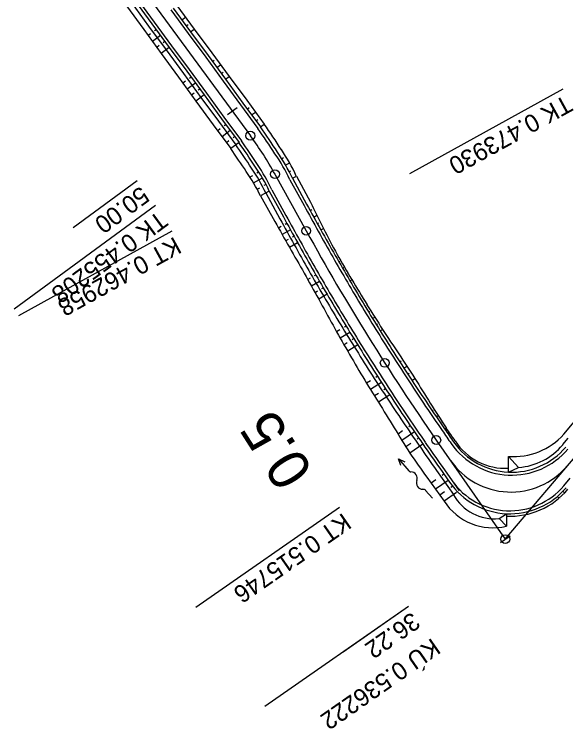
# Model space of a CAD drawing. Extents: x -481645 to -478728, y -1113199 to -1110710.
# Drawn here: x -480674.3 to -480580.8, y -1112993.4 to -1112872.3 of the extents above; entities that cross this region are included whole.
import ezdxf

# ---------------------------------------------------------------- set-up
doc = ezdxf.new("R2010")
doc.units = 0
for name, color, linetype in [('CP14_HATCH_SLOPE_R', 7, 'Continuous'), ('CP14_HECTOMETRY', 7, 'Continuous'), ('CP14_HLBODY', 7, 'Continuous'), ('CP14_STANICENI', 7, 'Continuous'), ('Vrstva 31', 7, 'Continuous'), ('Vrstva 32', 7, 'Continuous'), ('Vrstva 33', 7, 'Continuous'), ('Vrstva 34', 7, 'Continuous'), ('Vrstva 35', 7, 'Continuous'), ('Vrstva 36', 7, 'Continuous'), ('Vrstva 37', 7, 'Continuous'), ('Vrstva 38', 7, 'Continuous'), ('Vrstva 39', 7, 'Continuous'), ('Vrstva 40', 7, 'Continuous'), ('Vrstva 52', 7, 'Continuous'), ('Vrstva 53', 7, 'Continuous'), ('Vrstva 54', 7, 'Continuous'), ('Vrstva 56', 7, 'Continuous'), ('Vrstva 59', 7, 'Continuous'), ('Vrstva 60', 7, 'Continuous'), ('Vrstva 62', 7, 'Continuous')]:
    doc.layers.add(name, color=color, linetype=linetype)

# ---------------------------------------------------------------- blocks, each defined once
blk = doc.blocks.new('A$C70B')
at = {"layer": 'CP14_HLBODY'}
for p, q in [((0.87, 0), (-0.87, 0)), ((6.86, 0.43), (7.97, 0)), ((7.97, 0), (5.28, 0)), ((7.97, 0), (6.86, -0.48))]:
    blk.add_line(p, q, dxfattribs=at)
for centre, radius, start, end in [((0.87, 0.58), 0.582, 269.6924, 322.7901), ((2.17, -0.42), 1.05, 24.4039, 142.0836), ((4.08, 0.59), 1.11, 210.8873, 317.3707), ((5.32, -0.64), 0.636, 85.9766, 131.7248)]:
    blk.add_arc(centre, radius, start, end, dxfattribs=at)

msp = doc.modelspace()

# ---------------------------------------------------------------- linework, layer by layer
at = {"layer": 'CP14_HATCH_SLOPE_R'}
for p, q in [((-480664.72, -1112851.37), (-480634.28, -1112892.85)), ((-480630.11, -1112899.38), (-480624.81, -1112908.99)), ((-480602.74, -1112944.48), (-480591.03, -1112961.28))]:
    msp.add_line(p, q, dxfattribs=at)
for centre, radius, start, end in [((-480682.64, -1112928.36), 60, 28.8789, 36.2792), ((-480274.55, -1112715.8), 400, 208.8788, 214.8684)]:
    msp.add_arc(centre, radius, start, end, dxfattribs=at)
at = {"layer": 'CP14_STANICENI'}
for p, q in [((-480590.5, -1112949.92), (-480590.47, -1112947.25)), ((-480588.77, -1112949.11), (-480590.47, -1112947.25)), ((-480590.5, -1112949.92), (-480588.77, -1112949.11)), ((-480592.09, -1112957.8), (-480590.83, -1112956.97)), ((-480590.84, -1112959.08), (-480592.09, -1112957.8)), ((-480590.83, -1112956.97), (-480590.84, -1112959.08))]:
    msp.add_line(p, q, dxfattribs=at)
for centre, radius, start, end in [((-480589.58, -1112935.89), 11.4, 265.5343, 318.151), ((-480589.94, -1112937.91), 12.52, 214.9729, 319.6999), ((-480589.94, -1112937.91), 12.02, 214.9901, 319.698), ((-480591, -1112939.1), 10.17, 212.932, 273.0058), ((-480589.47, -1112938.55), 10.59, 273.8091, 320.6838), ((-480590.07, -1112940.8), 12.5, 214.8684, 319.744), ((-480590.24, -1112944.48), 12.5, 214.8684, 319.744), ((-480590.24, -1112944.48), 12, 214.8684, 319.744), ((-480590.24, -1112944.48), 12.91, 267.3062, 319.744), ((-480592.82, -1112949.79), 8.05, 209.4121, 275.245), ((-480593.17, -1112949.64), 9.72, 212.2087, 283.8922)]:
    msp.add_arc(centre, radius, start, end, dxfattribs=at)
at = {"layer": 'Vrstva 31'}
for p, q in [((-480655.3, -1112870.81), (-480652.35, -1112874.85)), ((-480646.77, -1112870.75), (-480643.8, -1112874.77)), ((-480652.35, -1112874.85), (-480649.41, -1112878.89)), ((-480643.8, -1112874.77), (-480640.83, -1112878.8)), ((-480649.41, -1112878.89), (-480646.46, -1112882.93)), ((-480640.83, -1112878.8), (-480637.86, -1112882.82)), ((-480646.46, -1112882.93), (-480643.51, -1112886.97)), ((-480637.86, -1112882.82), (-480634.9, -1112886.85)), ((-480643.51, -1112886.97), (-480640.57, -1112891.01)), ((-480634.9, -1112886.85), (-480631.93, -1112890.87)), ((-480640.57, -1112891.01), (-480637.62, -1112895.05)), ((-480626.48, -1112899.71), (-480624.1, -1112904.1)), ((-480632.56, -1112903.06), (-480630.11, -1112907.42)), ((-480604.34, -1112950.78), (-480601.4, -1112954.82))]:
    msp.add_line(p, q, dxfattribs=at)
for centre, radius, start, end in [((-480787.47, -1112998.49), 189.14, 33.0917, 34.6799), ((-480775.06, -1112991.79), 168.07, 33.5443, 35.1399), ((-480655.13, -1112912.86), 31.52, 24.6601, 34.0294), ((-480657.89, -1112915.03), 28.01, 25.2754, 35.1138), ((-479554.4, -1112378.75), 1191.74, 206.15703, 206.39731), ((-479573.29, -1112315.01), 1211.54, 209.27317, 209.51012), ((-480269.1, -1112725.81), 397.32, 207.3887, 208.1052), ((-480276.26, -1112712.8), 403.82, 209.5225, 210.2388), ((-480274.92, -1112715.17), 397.39, 209.8541, 210.5703), ((-480270.51, -1112722.94), 403.85, 208.5849, 209.3012), ((-480276.16, -1112713.12), 397.36, 210.9152, 211.6315), ((-480267.66, -1112727.81), 403.99, 208.5011, 209.2177), ((-480277.16, -1112711.61), 397.31, 211.8922, 212.6085), ((-480267.45, -1112727.83), 404.17, 209.1997, 209.9163), ((-480279.02, -1112708.87), 397.23, 213.0863, 213.8026), ((-480267.36, -1112727.64), 404.34, 209.9347, 210.6513), ((-480276.12, -1112713.4), 397.16, 213.0273, 213.7435), ((-480270.28, -1112722.52), 404.48, 211.485, 212.2014), ((-480267.71, -1112726.43), 397.22, 211.5063, 212.2229), ((-480266.47, -1112728.42), 404.62, 211.2066, 211.9233), ((-480268.31, -1112725.2), 397.37, 212.4186, 213.1351), ((-480265.04, -1112730.35), 404.82, 211.5848, 212.3017), ((-480654, -1112980.47), 65.2, 33.3455, 35.7109), ((-480439.82, -1112832.78), 202.47, 214.2314, 215.649)]:
    msp.add_arc(centre, radius, start, end, dxfattribs=at)
at = {"layer": 'Vrstva 32'}
for p, q in [((-480654.5, -1112870.23), (-480651.54, -1112874.26)), ((-480651.54, -1112874.26), (-480648.59, -1112878.29)), ((-480648.59, -1112878.29), (-480645.63, -1112882.32)), ((-480645.63, -1112882.32), (-480642.67, -1112886.35)), ((-480642.67, -1112886.35), (-480639.71, -1112890.38)), ((-480639.71, -1112890.38), (-480636.75, -1112894.41)), ((-480631.67, -1112902.57), (-480629.26, -1112906.95)), ((-480602.7, -1112949.64), (-480599.84, -1112953.74))]:
    msp.add_line(p, q, dxfattribs=at)
for centre, radius, start, end in [((-480777.22, -1112992.36), 171.25, 33.2939, 34.8884), ((-480657.58, -1112914.55), 28.54, 24.8176, 34.5767), ((-479569.79, -1112325.07), 1208.75, 208.77664, 209.01402), ((-480274.55, -1112715.8), 402.92, 209.0321, 209.7483), ((-480274.55, -1112715.8), 402.92, 209.7483, 210.4645), ((-480274.55, -1112715.8), 402.92, 210.4645, 211.1807), ((-480274.55, -1112715.8), 402.92, 211.1807, 211.8969), ((-480274.55, -1112715.8), 402.92, 211.8969, 212.6131), ((-480274.55, -1112715.8), 402.92, 212.6131, 213.3293), ((-480274.55, -1112715.8), 402.92, 213.3293, 214.0455), ((-480274.55, -1112715.8), 402.92, 214.0455, 214.7617), ((-480438.83, -1112832.44), 201.46, 214.1486, 215.5722)]:
    msp.add_arc(centre, radius, start, end, dxfattribs=at)
at = {"layer": 'Vrstva 33'}
for p, q in [((-480653.97, -1112869.83), (-480651.01, -1112873.86)), ((-480647.38, -1112871.2), (-480644.42, -1112875.23)), ((-480651.01, -1112873.86), (-480648.05, -1112877.89)), ((-480644.42, -1112875.23), (-480641.46, -1112879.26)), ((-480648.05, -1112877.89), (-480645.09, -1112881.92)), ((-480641.46, -1112879.26), (-480638.5, -1112883.29)), ((-480645.09, -1112881.92), (-480642.13, -1112885.95)), ((-480638.5, -1112883.29), (-480635.54, -1112887.32)), ((-480642.13, -1112885.95), (-480639.17, -1112889.99)), ((-480635.54, -1112887.32), (-480632.59, -1112891.35)), ((-480639.17, -1112889.99), (-480636.21, -1112894.02)), ((-480627.15, -1112900.08), (-480624.73, -1112904.46)), ((-480631.09, -1112902.25), (-480628.67, -1112906.63)), ((-480602.15, -1112949.26), (-480600.5, -1112951.63))]:
    msp.add_line(p, q, dxfattribs=at)
for centre, radius, start, end in [((-480785.79, -1112998.14), 186.75, 33.2888, 34.8776), ((-480778.33, -1112993.11), 173.25, 33.2932, 34.8869), ((-480655.35, -1112913.24), 31.12, 25.0179, 34.4356), ((-480657.29, -1112914.39), 28.88, 24.8453, 34.5569), ((-479578.83, -1112330.06), 1193.25, 208.77527, 209.01506), ((-479570.95, -1112325.71), 1206.75, 208.77647, 209.01415), ((-480274.55, -1112715.8), 397.75, 209.0321, 209.7483), ((-480274.55, -1112715.8), 402.25, 209.0321, 209.7483), ((-480274.55, -1112715.8), 397.75, 209.7483, 210.4645), ((-480274.55, -1112715.8), 402.25, 209.7483, 210.4645), ((-480274.55, -1112715.8), 397.75, 210.4645, 211.1807), ((-480274.55, -1112715.8), 402.25, 210.4645, 211.1807), ((-480274.55, -1112715.8), 397.75, 211.1807, 211.8969), ((-480274.55, -1112715.8), 402.25, 211.1807, 211.8969), ((-480274.55, -1112715.8), 397.75, 211.8969, 212.6131), ((-480274.55, -1112715.8), 402.25, 211.8969, 212.6131), ((-480274.55, -1112715.8), 397.75, 212.6131, 213.3293), ((-480274.55, -1112715.8), 402.25, 212.6131, 213.3293), ((-480274.55, -1112715.8), 397.75, 213.3293, 214.0455), ((-480274.55, -1112715.8), 402.25, 213.3293, 214.0455), ((-480274.55, -1112715.8), 397.75, 214.0455, 214.7617), ((-480274.55, -1112715.8), 402.25, 214.0455, 214.7617), ((-480436.71, -1112830.97), 198.88, 214.1408, 214.9166), ((-480438.56, -1112832.25), 201.12, 214.1476, 215.5732)]:
    msp.add_arc(centre, radius, start, end, dxfattribs=at)
at = {"layer": 'Vrstva 34'}
for p, q in [((-480653.56, -1112869.53), (-480650.6, -1112873.57)), ((-480647.78, -1112871.5), (-480644.82, -1112875.53)), ((-480650.6, -1112873.57), (-480647.64, -1112877.6)), ((-480644.82, -1112875.53), (-480641.86, -1112879.56)), ((-480647.64, -1112877.6), (-480644.69, -1112881.63)), ((-480641.86, -1112879.56), (-480638.91, -1112883.59)), ((-480644.69, -1112881.63), (-480641.73, -1112885.66)), ((-480638.91, -1112883.59), (-480635.95, -1112887.62)), ((-480641.73, -1112885.66), (-480638.77, -1112889.69)), ((-480635.95, -1112887.62), (-480632.99, -1112891.65)), ((-480638.77, -1112889.69), (-480635.81, -1112893.72)), ((-480627.59, -1112900.32), (-480625.17, -1112904.7)), ((-480630.65, -1112902.01), (-480628.24, -1112906.39)), ((-480601.74, -1112948.97), (-480598.88, -1112953.07))]:
    msp.add_line(p, q, dxfattribs=at)
for centre, radius, start, end in [((-480784.96, -1112997.58), 185.25, 33.2893, 34.8785), ((-480779.16, -1112993.67), 174.75, 33.2927, 34.8858), ((-480655.57, -1112913.37), 30.88, 24.9999, 34.4481), ((-480657.08, -1112914.26), 29.12, 24.8657, 34.5424), ((-479577.96, -1112329.57), 1194.75, 208.7754, 209.01496), ((-479571.83, -1112326.19), 1205.25, 208.77634, 209.01425), ((-480274.55, -1112715.8), 398.25, 209.0321, 209.7483), ((-480274.55, -1112715.8), 401.75, 209.0321, 209.7483), ((-480274.55, -1112715.8), 398.25, 209.7483, 210.4645), ((-480274.55, -1112715.8), 401.75, 209.7483, 210.4645), ((-480274.55, -1112715.8), 398.25, 210.4645, 211.1807), ((-480274.55, -1112715.8), 401.75, 210.4645, 211.1807), ((-480274.55, -1112715.8), 398.25, 211.1807, 211.8969), ((-480274.55, -1112715.8), 401.75, 211.1807, 211.8969), ((-480274.55, -1112715.8), 398.25, 211.8969, 212.6131), ((-480274.55, -1112715.8), 401.75, 211.8969, 212.6131), ((-480274.55, -1112715.8), 398.25, 212.6131, 213.3293), ((-480274.55, -1112715.8), 401.75, 212.6131, 213.3293), ((-480274.55, -1112715.8), 398.25, 213.3293, 214.0455), ((-480274.55, -1112715.8), 401.75, 213.3293, 214.0455), ((-480274.55, -1112715.8), 398.25, 214.0455, 214.7617), ((-480274.55, -1112715.8), 401.75, 214.0455, 214.7617), ((-480436.92, -1112831.11), 199.12, 214.1416, 214.9159), ((-480438.36, -1112832.11), 200.88, 214.1468, 215.574)]:
    msp.add_arc(centre, radius, start, end, dxfattribs=at)
at = {"layer": 'Vrstva 35'}
for p, q in [((-480653.56, -1112869.53), (-480650.6, -1112873.57)), ((-480647.78, -1112871.5), (-480644.82, -1112875.53)), ((-480650.6, -1112873.57), (-480647.64, -1112877.6)), ((-480644.82, -1112875.53), (-480641.86, -1112879.56)), ((-480647.64, -1112877.6), (-480644.69, -1112881.63)), ((-480641.86, -1112879.56), (-480638.91, -1112883.59)), ((-480644.69, -1112881.63), (-480641.73, -1112885.66)), ((-480638.91, -1112883.59), (-480635.95, -1112887.62)), ((-480641.73, -1112885.66), (-480638.77, -1112889.69)), ((-480635.95, -1112887.62), (-480632.99, -1112891.65)), ((-480638.77, -1112889.69), (-480635.81, -1112893.72)), ((-480627.59, -1112900.32), (-480625.17, -1112904.7)), ((-480630.65, -1112902.01), (-480628.24, -1112906.39)), ((-480601.74, -1112948.97), (-480598.88, -1112953.07))]:
    msp.add_line(p, q, dxfattribs=at)
for centre, radius, start, end in [((-480784.96, -1112997.58), 185.25, 33.2893, 34.8785), ((-480779.16, -1112993.67), 174.75, 33.2927, 34.8858), ((-480655.57, -1112913.37), 30.88, 24.9999, 34.4481), ((-480657.08, -1112914.26), 29.12, 24.8657, 34.5424), ((-479577.96, -1112329.57), 1194.75, 208.7754, 209.01496), ((-479571.83, -1112326.19), 1205.25, 208.77634, 209.01425), ((-480274.55, -1112715.8), 398.25, 209.0321, 209.7483), ((-480274.55, -1112715.8), 401.75, 209.0321, 209.7483), ((-480274.55, -1112715.8), 398.25, 209.7483, 210.4645), ((-480274.55, -1112715.8), 401.75, 209.7483, 210.4645), ((-480274.55, -1112715.8), 398.25, 210.4645, 211.1807), ((-480274.55, -1112715.8), 401.75, 210.4645, 211.1807), ((-480274.55, -1112715.8), 398.25, 211.1807, 211.8969), ((-480274.55, -1112715.8), 401.75, 211.1807, 211.8969), ((-480274.55, -1112715.8), 398.25, 211.8969, 212.6131), ((-480274.55, -1112715.8), 401.75, 211.8969, 212.6131), ((-480274.55, -1112715.8), 398.25, 212.6131, 213.3293), ((-480274.55, -1112715.8), 401.75, 212.6131, 213.3293), ((-480274.55, -1112715.8), 398.25, 213.3293, 214.0455), ((-480274.55, -1112715.8), 401.75, 213.3293, 214.0455), ((-480274.55, -1112715.8), 398.25, 214.0455, 214.7617), ((-480274.55, -1112715.8), 401.75, 214.0455, 214.7617), ((-480436.92, -1112831.11), 199.12, 214.1416, 214.9159), ((-480438.36, -1112832.11), 200.88, 214.1468, 215.574)]:
    msp.add_arc(centre, radius, start, end, dxfattribs=at)
at = {"layer": 'Vrstva 36'}
for p, q in [((-480638.16, -1112889.25), (-480636.55, -1112888.06)), ((-480653.48, -1112900.49), (-480664.36, -1112908.48)), ((-480591.85, -1112961.85), (-480590.21, -1112960.71)), ((-480607.44, -1112972.71), (-480618.52, -1112980.43))]:
    msp.add_line(p, q, dxfattribs=at)
at = {"layer": 'Vrstva 37'}
for p, q in [((-480581.29, -1112884.98), (-480607.29, -1112899.33)), ((-480650.4, -1112904.69), (-480674.34, -1112922.26)), ((-480647.62, -1112909.04), (-480673.62, -1112923.38)), ((-480619.15, -1112955.91), (-480643.51, -1112972.89)), ((-480607.44, -1112972.71), (-480631.81, -1112989.69))]:
    msp.add_line(p, q, dxfattribs=at)
for centre in [(-480634.28, -1112892.85), (-480630.11, -1112899.38), (-480624.81, -1112908.99), (-480602.74, -1112944.48), (-480591.03, -1112961.28)]:
    msp.add_circle(centre, 0.75, dxfattribs=at)
at = {"layer": 'Vrstva 38'}
msp.add_circle((-480611.48, -1112931.39), 0.75, dxfattribs=at)
at = {"layer": 'Vrstva 39'}
for p, q in [((-480645.9, -1112873.22), (-480645.28, -1112872.76)), ((-480645.16, -1112874.22), (-480644.85, -1112874)), ((-480644.54, -1112873.77), (-480644.54, -1112873.77)), ((-480644.42, -1112875.23), (-480643.8, -1112874.77)), ((-480640.72, -1112880.27), (-480640.4, -1112880.04)), ((-480640.09, -1112879.8), (-480640.09, -1112879.8)), ((-480639.98, -1112881.28), (-480639.35, -1112880.81)), ((-480639.24, -1112882.28), (-480638.92, -1112882.05)), ((-480638.6, -1112881.82), (-480638.6, -1112881.82)), ((-480638.5, -1112883.29), (-480637.86, -1112882.82)), ((-480634.8, -1112888.33), (-480634.48, -1112888.09)), ((-480634.15, -1112887.85), (-480634.15, -1112887.85)), ((-480634.07, -1112889.34), (-480633.41, -1112888.86)), ((-480632.67, -1112889.86), (-480632.67, -1112889.86)), ((-480633.33, -1112890.34), (-480633, -1112890.1)), ((-480632.59, -1112891.35), (-480631.93, -1112890.87)), ((-480629.01, -1112896.75), (-480628.67, -1112896.55)), ((-480628.34, -1112896.35), (-480628.34, -1112896.35)), ((-480628.37, -1112897.88), (-480627.69, -1112897.5)), ((-480627.75, -1112898.99), (-480627.42, -1112898.8)), ((-480627.08, -1112898.61), (-480627.08, -1112898.61)), ((-480627.15, -1112900.08), (-480626.48, -1112899.71)), ((-480624.13, -1112905.55), (-480623.84, -1112905.39)), ((-480623.54, -1112905.23), (-480623.54, -1112905.23)), ((-480623.53, -1112906.65), (-480622.99, -1112906.35)), ((-480622.92, -1112907.74), (-480622.68, -1112907.61)), ((-480622.43, -1112907.47), (-480622.43, -1112907.47)), ((-480622.32, -1112908.83), (-480621.88, -1112908.59)), ((-480619.26, -1112914.24), (-480619.11, -1112914.15)), ((-480618.95, -1112914.06), (-480618.95, -1112914.06)), ((-480618.64, -1112915.32), (-480618.33, -1112915.13)), ((-480618.02, -1112916.39), (-480617.86, -1112916.3)), ((-480617.7, -1112916.21), (-480617.7, -1112916.21)), ((-480617.39, -1112917.46), (-480617.07, -1112917.28)), ((-480614.2, -1112922.79), (-480614.01, -1112922.68)), ((-480613.83, -1112922.57), (-480613.83, -1112922.57)), ((-480613.55, -1112923.85), (-480613.17, -1112923.63)), ((-480612.9, -1112924.91), (-480612.7, -1112924.79)), ((-480612.51, -1112924.68), (-480612.51, -1112924.68)), ((-480612.24, -1112925.97), (-480611.84, -1112925.72)), ((-480608.92, -1112931.22), (-480608.67, -1112931.06)), ((-480608.42, -1112930.91), (-480608.42, -1112930.91)), ((-480608.24, -1112932.26), (-480607.74, -1112931.94)), ((-480607.56, -1112933.31), (-480607.31, -1112933.14)), ((-480607.06, -1112932.98), (-480607.06, -1112932.98)), ((-480606.88, -1112934.35), (-480606.37, -1112934.01)), ((-480603.42, -1112939.51), (-480603.25, -1112939.39)), ((-480603.08, -1112939.28), (-480603.08, -1112939.28)), ((-480602.73, -1112940.54), (-480602.41, -1112940.32)), ((-480602.02, -1112941.56), (-480601.88, -1112941.46)), ((-480601.74, -1112941.37), (-480601.74, -1112941.37)), ((-480601.31, -1112942.58), (-480601.06, -1112942.41))]:
    msp.add_line(p, q, dxfattribs=at)
at = {"layer": 'Vrstva 40'}
for p, q in [((-480650.27, -1112874.87), (-480650.54, -1112875.07)), ((-480651.21, -1112875.56), (-480651.62, -1112875.86)), ((-480649.53, -1112875.88), (-480650.88, -1112876.87)), ((-480649.73, -1112877.58), (-480650.15, -1112877.88)), ((-480648.79, -1112876.89), (-480649.06, -1112877.08)), ((-480648.05, -1112877.89), (-480649.41, -1112878.89)), ((-480645.3, -1112883.63), (-480645.72, -1112883.94)), ((-480644.35, -1112882.93), (-480644.62, -1112883.13)), ((-480643.61, -1112883.94), (-480644.99, -1112884.95)), ((-480642.87, -1112884.95), (-480643.14, -1112885.14)), ((-480643.83, -1112885.65), (-480644.25, -1112885.96)), ((-480642.13, -1112885.95), (-480643.51, -1112886.97)), ((-480638.43, -1112890.99), (-480638.7, -1112891.19)), ((-480639.4, -1112891.7), (-480639.83, -1112892.02)), ((-480637.69, -1112892), (-480639.09, -1112893.03)), ((-480636.95, -1112893.01), (-480637.22, -1112893.21)), ((-480637.92, -1112893.72), (-480638.36, -1112894.04)), ((-480636.21, -1112894.02), (-480637.62, -1112895.05)), ((-480633.92, -1112899.64), (-480634.37, -1112899.91)), ((-480632.89, -1112899.04), (-480633.18, -1112899.21)), ((-480632.29, -1112900.08), (-480633.78, -1112900.91)), ((-480632.73, -1112901.73), (-480633.18, -1112901.98)), ((-480631.69, -1112901.16), (-480631.99, -1112901.32)), ((-480631.09, -1112902.25), (-480632.56, -1112903.06)), ((-480628.07, -1112907.73), (-480628.36, -1112907.89)), ((-480629.08, -1112908.28), (-480629.5, -1112908.51)), ((-480627.47, -1112908.82), (-480628.88, -1112909.6)), ((-480627.86, -1112910.46), (-480628.27, -1112910.69)), ((-480626.86, -1112909.91), (-480627.16, -1112910.07)), ((-480626.26, -1112911.01), (-480627.65, -1112911.79)), ((-480623.16, -1112916.49), (-480623.45, -1112916.65)), ((-480624.14, -1112917.04), (-480624.53, -1112917.27)), ((-480622.53, -1112917.57), (-480623.92, -1112918.38)), ((-480621.9, -1112918.66), (-480622.19, -1112918.83)), ((-480622.89, -1112919.24), (-480623.31, -1112919.48)), ((-480621.27, -1112919.74), (-480622.69, -1112920.58)), ((-480619.12, -1112925.8), (-480619.64, -1112926.11)), ((-480617.38, -1112926.21), (-480619.02, -1112927.21)), ((-480618.04, -1112925.14), (-480618.32, -1112925.31)), ((-480616.72, -1112927.28), (-480617.01, -1112927.45)), ((-480617.84, -1112927.97), (-480618.39, -1112928.31)), ((-480616.06, -1112928.35), (-480617.76, -1112929.41)), ((-480613.9, -1112934.43), (-480614.55, -1112934.85)), ((-480612.02, -1112934.71), (-480613.88, -1112935.93)), ((-480612.7, -1112933.66), (-480612.98, -1112933.84)), ((-480611.33, -1112935.77), (-480611.61, -1112935.95)), ((-480612.55, -1112936.56), (-480613.21, -1112937)), ((-480610.64, -1112936.82), (-480612.54, -1112938.07)), ((-480607.15, -1112942.04), (-480607.42, -1112942.23)), ((-480608.46, -1112942.94), (-480609.23, -1112943.46)), ((-480606.44, -1112943.08), (-480608.56, -1112944.53)), ((-480605.73, -1112944.12), (-480606, -1112944.31)), ((-480607.08, -1112945.05), (-480607.89, -1112945.61)), ((-480605.01, -1112945.15), (-480607.21, -1112946.68)), ((-480601.44, -1112950.28), (-480601.71, -1112950.47)), ((-480602.79, -1112951.23), (-480603.61, -1112951.79)), ((-480600.72, -1112951.31), (-480602.87, -1112952.8)), ((-480600.01, -1112952.33), (-480600.28, -1112952.52)), ((-480601.34, -1112953.26), (-480602.13, -1112953.81)), ((-480599.29, -1112953.36), (-480601.4, -1112954.82))]:
    msp.add_line(p, q, dxfattribs=at)
at = {"layer": 'Vrstva 52'}
msp.add_line((-480591.03, -1112961.28), (-480529.75, -1112888.91), dxfattribs=at)
at = {"layer": 'Vrstva 53'}
msp.add_line((-480581.09, -1112943.49), (-480577.89, -1112939.64), dxfattribs=at)
at = {"layer": 'Vrstva 54'}
msp.add_line((-480581.28, -1112945.25), (-480580.33, -1112944.13), dxfattribs=at)
at = {"layer": 'Vrstva 56'}
msp.add_line((-480581.08, -1112952.24), (-480580, -1112950.96), dxfattribs=at)
at = {"layer": 'Vrstva 59'}
msp.add_circle((-480591.03, -1112961.28), 0.75, dxfattribs=at)
at = {"layer": 'Vrstva 60'}
msp.add_circle((-480591.03, -1112961.28), 0.75, dxfattribs=at)
at = {"layer": 'Vrstva 62'}
for p, q in [((-480582.04, -1112954.15), (-480581.89, -1112954.28)), ((-480581.23, -1112953.19), (-480580.92, -1112953.46)), ((-480581.73, -1112954.42), (-480581.73, -1112954.42))]:
    msp.add_line(p, q, dxfattribs=at)

# ---------------------------------------------------------------- block references
at = {"layer": 'CP14_HECTOMETRY', "rotation": 130.73036552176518}
msp.add_blockref('A$C70B', (-480603.97, -1112953.69), dxfattribs=at)

# ---------------------------------------------------------------- texts
at = {"layer": 'Vrstva 36'}
for s, rotation, p in [('50.00', 216.2792, (-480652.89, -1112901.29)), ('36.22', 214.8685, (-480606.87, -1112973.53))]:
    msp.add_text(s, height=3, rotation=rotation, dxfattribs=at).set_placement(p)
at = {"layer": 'Vrstva 37'}
for s, rotation, p in [('TK 0.473930', 208.8789, (-480580.8, -1112885.86)), ('TK 0.455208', 216.2792, (-480649.81, -1112905.49)), ('KT 0.462958', 208.8789, (-480647.14, -1112909.91)), ('KT 0.515746', 214.8685, (-480618.57, -1112956.73)), ('KÚ 0.536222', 214.8685, (-480603.45, -1112977.95))]:
    msp.add_text(s, height=2.999, rotation=rotation, dxfattribs=at).set_placement(p)
at = {"layer": 'Vrstva 38'}
msp.add_text('0.5', height=6.999, rotation=122.5674, dxfattribs=at).set_placement((-480623.46, -1112949.79))

doc.saveas('drawing.dxf')
